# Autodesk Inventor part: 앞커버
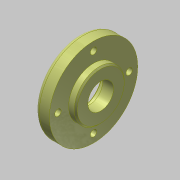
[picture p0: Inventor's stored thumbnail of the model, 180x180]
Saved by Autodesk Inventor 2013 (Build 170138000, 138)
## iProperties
Created: 2015-12
Part Number: 앞커버
Document SubType Name: Modeling
Designer: mdu
Density: 2.71 g/cm^3
Material: 알루미늄 6061
Mass: 70.9292 g
Surface Area: 93.9294 cm^2
Volume: 26.1731 cm^3
Author: mdu
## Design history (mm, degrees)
sketch "스케치1"
  geometry: L1 (-7.5, 0)-(7.5, 0); L2 (-7.5, 0)-(-7.5, 31); L3 (-7.5, 31)-(2.5, 31); L4 (2.5, 31)-(2.5, 17.5); L5 (2.5, 17.5)-(7.5, 17.5); L6 (7.5, 17.5)-(7.5, 0); 2 further points
  constraints: 12 end point, 3 perpendicular, 1 coincident, 1 horizontal, 1 midpoint, 1 parallel
  dimensions: "d0" = 15 distance of L1.start L1.end; "d1" = 62 diameter of L3 L1; "d2" = 35 diameter of L5 L1; "d5" = 10 distance of L2.end L3.end
revolve "회전1" sketch "스케치1" stored, may be unused: angle "d6" = 90 deg
sketch "스케치2" dims "d42" = 50
  geometry: 3 further points
  constraints: 2 vertical alignment, 1 coincident, 2 other
hole "구멍1" sketch "스케치2" at (0, 25) diameter "d8" = 4.5; stored, may be unused: countersink angle "d12" = 90 deg, drill point angle "d14" = 118 deg; dims "d9" = 6, "d10" = 8, "d11" = 4.4, "d13" = 8
hole "구멍2" diameter "d20" = 18; stored, may be unused: countersink angle "d24" = 90 deg, drill point angle "d26" = 0 deg; dims "d18" = 10, "d19" = 10, "d21" = 6, "d22" = 8, "d23" = 4.4, "d25" = 8
hole "구멍3" diameter "d34" = 30; stored, may be unused: countersink angle "d38" = 90 deg, drill point angle "d40" = 0 deg; dims "d32" = 10, "d33" = 10, "d35" = 6, "d36" = 4, "d37" = 2, "d39" = 7.3
fillet "모깎기1" dims "d27" = 3, "d41" = 0.3
chamfer "모따기1" distance "d29" = 1; stored, may be unused: second distance "d30" = 2, angle "d31" = 45 deg
node "솔리드1"
pattern_circular "원형 패턴1" dims angle "d16" = 360 deg
